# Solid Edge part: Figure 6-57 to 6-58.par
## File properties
Author: Ashutosh-CADCIM
Template: Iso Metric Part.par
Last saved by: Ashutosh-CADCIM
Revision: 1
Application: Solid Edge
Accuracy: 0.990
Username: Ashutosh-CADCIM
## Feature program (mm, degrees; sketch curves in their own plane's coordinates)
sketch for "unnamed Protrusion 1" plane through (0, 0, 0) normal (0, 0, 1) x-axis (1, 0, 0)
  line (-75, 100) -> (-75, -100)
  line (-75, -100) -> (75, -100)
  line (75, -100) -> (75, 100)
  line (75, 100) -> (-75, 100)
extrude "unnamed Protrusion 1" add finite 30 symmetric
sketch for "unnamed Cutout 1" plane through (0, 0, 15) normal (0, 0, 1) x-axis (0, 1, 0)
  line (-48.9253, 43.9807) -> (-85.359, 43.9807)
  line (-85.359, 43.9807) -> (-85.359, 58.5542)
  line (-85.359, 58.5542) -> (-48.9253, 58.5542)
  line (-48.9253, 58.5542) -> (-48.9253, 43.9807)
extrude "unnamed Cutout 1" cut through along -normal
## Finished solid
Body 1: solid body, 10 faces, 24 edges, 16 vertices.
  Faces by surface: plane 10
  Edges by curve: line 24
Bounding box of the edges (mm): 150.000 x 200.000 x 30.000, from (-75, -100, -15) to (75, 100, 15).
Planar faces by outward normal: +x 2, +y 2, +z 1, -x 2, -y 2, -z 1
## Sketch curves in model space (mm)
spline (-51.2675, -67.1422, 15) -> (61.97, 61.0363, 15) -> (-48.6651, 72.0867, 15)
line (75, -100, 0) -> (75, 100, 0)
line (75, 100, 0) -> (-75, 100, 0)
line (-75, 100, 0) -> (-75, -100, 0)
line (-75, -100, 0) -> (75, -100, 0)
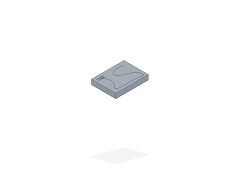
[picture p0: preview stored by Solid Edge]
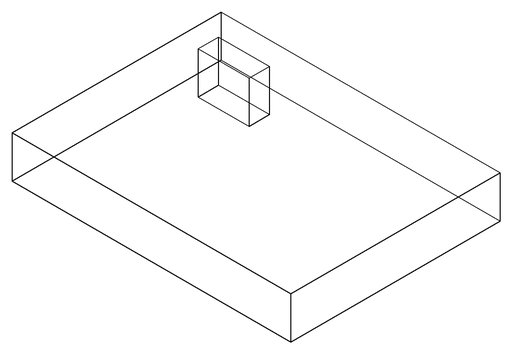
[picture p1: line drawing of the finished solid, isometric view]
